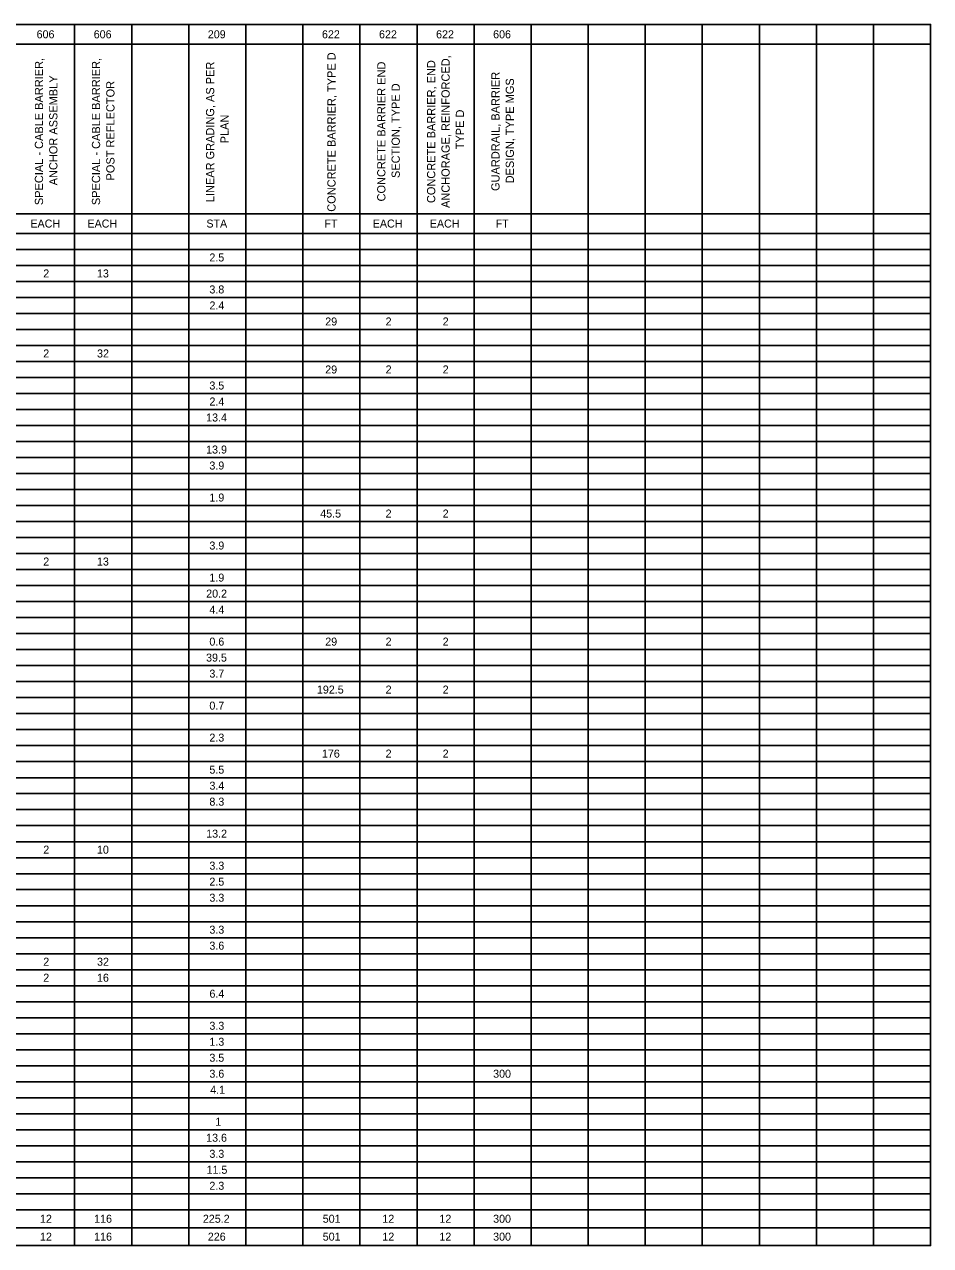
# Model space of a CAD drawing. Extents: x -542 to 295, y -281 to 32.
# Drawn here: x -1.5 to 14.08, y -100.59 to -79.59 of the extents above; entities that cross this region are included whole.
import ezdxf

# ---------------------------------------------------------------- set-up
doc = ezdxf.new("R2010")
doc.units = 0
doc.layers.add('SC_Scratch1', color=7, linetype='Continuous')
doc.layers.add('SH_Text', color=7, linetype='Continuous')

msp = doc.modelspace()

# ---------------------------------------------------------------- linework, layer by layer
at = {"layer": 'SC_Scratch1'}
msp.add_lwpolyline([(-16.421, -79.593), (14.079, -79.593), (14.079, -100.593), (-16.421, -100.593)], close=True, dxfattribs=at)
at = {"layer": 'SH_Text'}
for p, q in [((-16.421, -79.593), (14.079, -79.593)), ((-0.639, -79.593), (-0.639, -100.593)), ((0.342, -79.593), (0.342, -100.593)), ((1.324, -79.593), (1.324, -100.593)), ((2.305, -79.593), (2.305, -100.593)), ((3.286, -79.593), (3.286, -100.593)), ((4.267, -79.593), (4.267, -100.593)), ((5.248, -79.593), (5.248, -100.593)), ((6.23, -79.593), (6.23, -100.593)), ((7.211, -79.593), (7.211, -100.593)), ((8.192, -79.593), (8.192, -100.593)), ((9.173, -79.593), (9.173, -100.593)), ((10.154, -79.593), (10.154, -100.593)), ((11.136, -79.593), (11.136, -100.593)), ((12.117, -79.593), (12.117, -100.593)), ((13.098, -79.593), (13.098, -100.593)), ((14.079, -79.593), (14.079, -100.593)), ((-9.469, -79.933), (14.079, -79.933)), ((-9.469, -82.847), (14.079, -82.847)), ((-16.421, -83.187), (14.079, -83.187)), ((-16.421, -83.462), (14.079, -83.462)), ((-16.421, -83.737), (14.079, -83.737)), ((-16.421, -84.013), (14.079, -84.013)), ((-16.421, -84.288), (14.079, -84.288)), ((-16.421, -84.563), (14.079, -84.563)), ((-16.421, -84.838), (14.079, -84.838)), ((-16.421, -85.114), (14.079, -85.114)), ((-16.421, -85.389), (14.079, -85.389)), ((-16.421, -85.664), (14.079, -85.664)), ((-16.421, -85.94), (14.079, -85.94)), ((-16.421, -86.215), (14.079, -86.215)), ((-16.421, -86.49), (14.079, -86.49)), ((-16.421, -86.765), (14.079, -86.765)), ((-16.421, -87.041), (14.079, -87.041)), ((-16.421, -87.316), (14.079, -87.316)), ((-16.421, -87.591), (14.079, -87.591)), ((-16.421, -87.866), (14.079, -87.866)), ((-16.421, -88.142), (14.079, -88.142)), ((-16.421, -88.417), (14.079, -88.417)), ((-16.421, -88.692), (14.079, -88.692)), ((-16.421, -88.967), (14.079, -88.967)), ((-16.421, -89.243), (14.079, -89.243)), ((-16.421, -89.518), (14.079, -89.518)), ((-16.421, -89.793), (14.079, -89.793)), ((-16.421, -90.068), (14.079, -90.068)), ((-16.421, -90.344), (14.079, -90.344)), ((-16.421, -90.619), (14.079, -90.619)), ((-16.421, -90.894), (14.079, -90.894)), ((-16.421, -91.169), (14.079, -91.169)), ((-16.421, -91.445), (14.079, -91.445)), ((-16.421, -91.72), (14.079, -91.72)), ((-16.421, -91.995), (14.079, -91.995)), ((-16.421, -92.27), (14.079, -92.27)), ((-16.421, -92.546), (14.079, -92.546)), ((-16.421, -92.821), (14.079, -92.821)), ((-16.421, -93.096), (14.079, -93.096)), ((-16.421, -93.371), (14.079, -93.371)), ((-16.421, -93.647), (14.079, -93.647)), ((-16.421, -93.922), (14.079, -93.922)), ((-16.421, -94.197), (14.079, -94.197)), ((-16.421, -94.472), (14.079, -94.472)), ((-16.421, -94.748), (14.079, -94.748)), ((-16.421, -95.023), (14.079, -95.023)), ((-16.421, -95.298), (14.079, -95.298)), ((-16.421, -95.573), (14.079, -95.573)), ((-16.421, -95.849), (14.079, -95.849)), ((-16.421, -96.124), (14.079, -96.124)), ((-16.421, -96.399), (14.079, -96.399)), ((-16.421, -96.674), (14.079, -96.674)), ((-16.421, -96.95), (14.079, -96.95)), ((-16.421, -97.225), (14.079, -97.225)), ((-16.421, -97.5), (14.079, -97.5)), ((-16.421, -97.775), (14.079, -97.775)), ((-16.421, -98.051), (14.079, -98.051)), ((-16.421, -98.326), (14.079, -98.326)), ((-16.421, -98.601), (14.079, -98.601)), ((-16.421, -98.876), (14.079, -98.876)), ((-16.421, -99.152), (14.079, -99.152)), ((-16.421, -99.427), (14.079, -99.427)), ((-16.421, -99.702), (14.079, -99.702)), ((-16.421, -99.977), (14.079, -99.977)), ((-16.421, -100.285), (14.079, -100.285)), ((-16.421, -100.593), (14.079, -100.593))]:
    msp.add_line(p, q, dxfattribs=at)

# ---------------------------------------------------------------- texts
for s, height, p in [('606', 0.1376, (-1.293, -79.831)), ('606', 0.1376, (-0.311, -79.831)), ('209', 0.1376, (1.651, -79.831)), ('622', 0.1376, (3.614, -79.831)), ('622', 0.1376, (4.595, -79.831)), ('622', 0.1376, (5.576, -79.831)), ('606', 0.1376, (6.557, -79.831)), ('EACH', 0.1376, (-1.4, -83.086)), ('EACH', 0.1376, (-0.419, -83.086)), ('STA', 0.1376, (1.626, -83.086)), ('FT', 0.1376, (3.656, -83.086)), ('EACH', 0.1376, (4.487, -83.086)), ('EACH', 0.1376, (5.468, -83.086)), ('FT', 0.1376, (6.6, -83.086)), ('2.5', 0.1376, (1.678, -83.669)), ('2', 0.138, (-1.179, -83.944)), ('13', 0.1376, (-0.255, -83.944)), ('3.8', 0.1376, (1.678, -84.219)), ('2.4', 0.1376, (1.679, -84.494)), ('29', 0.1376, (3.67, -84.77)), ('2', 0.138, (4.708, -84.77)), ('2', 0.138, (5.689, -84.77)), ('2', 0.138, (-1.179, -85.32)), ('32', 0.1376, (-0.254, -85.32)), ('29', 0.1376, (3.67, -85.595)), ('2', 0.138, (4.708, -85.595)), ('2', 0.138, (5.689, -85.595)), ('3.5', 0.1376, (1.678, -85.871)), ('2.4', 0.1376, (1.679, -86.146)), ('13.4', 0.1376, (1.622, -86.421)), ('13.9', 0.1376, (1.622, -86.972)), ('3.9', 0.1376, (1.678, -87.247)), ('1.9', 0.1376, (1.678, -87.797)), ('45.5', 0.1376, (3.584, -88.073)), ('2', 0.138, (4.708, -88.073)), ('2', 0.138, (5.689, -88.073)), ('3.9', 0.1376, (1.678, -88.623)), ('2', 0.138, (-1.179, -88.898)), ('13', 0.1376, (-0.255, -88.898)), ('1.9', 0.1376, (1.678, -89.174)), ('20.2', 0.1376, (1.623, -89.449)), ('4.4', 0.1376, (1.679, -89.724)), ('0.6', 0.1376, (1.678, -90.275)), ('29', 0.1376, (3.67, -90.275)), ('2', 0.138, (4.708, -90.275)), ('2', 0.138, (5.689, -90.275)), ('39.5', 0.1376, (1.621, -90.55)), ('3.7', 0.1376, (1.678, -90.825)), ('192.5', 0.1376, (3.527, -91.1)), ('2', 0.138, (4.708, -91.1)), ('2', 0.138, (5.689, -91.1)), ('0.7', 0.1376, (1.678, -91.376)), ('2.3', 0.1376, (1.678, -91.926)), ('176', 0.1376, (3.613, -92.201)), ('2', 0.138, (4.708, -92.201)), ('2', 0.138, (5.689, -92.201)), ('5.5', 0.1376, (1.678, -92.477)), ('3.4', 0.1376, (1.679, -92.752)), ('8.3', 0.1376, (1.678, -93.027)), ('13.2', 0.1376, (1.623, -93.578)), ('2', 0.138, (-1.179, -93.853)), ('10', 0.1376, (-0.255, -93.853)), ('3.3', 0.1376, (1.678, -94.128)), ('2.5', 0.1376, (1.678, -94.403)), ('3.3', 0.1376, (1.678, -94.679)), ('3.3', 0.1376, (1.678, -95.229)), ('3.6', 0.1376, (1.678, -95.504)), ('2', 0.138, (-1.179, -95.78)), ('32', 0.1376, (-0.254, -95.78)), ('2', 0.138, (-1.179, -96.055)), ('16', 0.1376, (-0.255, -96.055)), ('6.4', 0.1376, (1.679, -96.33)), ('3.3', 0.1376, (1.678, -96.881)), ('1.3', 0.1376, (1.678, -97.156)), ('3.5', 0.1376, (1.678, -97.431)), ('3.6', 0.1376, (1.678, -97.706)), ('300', 0.1376, (6.557, -97.706)), ('4.1', 0.1376, (1.692, -97.982)), ('1', 0.138, (1.778, -98.532)), ('13.6', 0.1376, (1.622, -98.807)), ('3.3', 0.1376, (1.678, -99.083)), ('11.5', 0.1376, (1.629, -99.358)), ('2.3', 0.1376, (1.678, -99.633)), ('12', 0.1376, (-1.235, -100.2)), ('116', 0.1376, (-0.304, -100.2)), ('225.2', 0.1376, (1.566, -100.2)), ('501', 0.1376, (3.627, -100.2)), ('12', 0.1376, (4.652, -100.2)), ('12', 0.1376, (5.633, -100.2)), ('300', 0.1376, (6.557, -100.2)), ('12', 0.1376, (-1.235, -100.508)), ('116', 0.1376, (-0.304, -100.508)), ('226', 0.1376, (1.651, -100.508)), ('501', 0.1376, (3.627, -100.508)), ('12', 0.1376, (4.652, -100.508)), ('12', 0.1376, (5.633, -100.508)), ('300', 0.1376, (6.557, -100.508))]:
    msp.add_text(s, height=height, dxfattribs=at).set_placement(p)
for s, height, p in [('SPECIAL - CABLE BARRIER, ', 0.14136, (-1.182, -82.7)), ('SPECIAL - CABLE BARRIER, ', 0.14136, (-0.201, -82.7)), ('CONCRETE BARRIER, TYPE D', 0.14136, (3.847, -82.814)), ('CONCRETE BARRIER, END ', 0.14136, (5.562, -82.665)), ('ANCHORAGE, REINFORCED, ', 0.14136, (5.81, -82.749)), ('LINEAR GRADING, AS PER ', 0.14136, (1.761, -82.649)), ('CONCRETE BARRIER END ', 0.14136, (4.705, -82.637)), ('GUARDRAIL, BARRIER ', 0.14136, (6.667, -82.456)), ('ANCHOR ASSEMBLY', 0.14136, (-0.935, -82.36)), ('POST REFLECTOR', 0.14136, (0.046, -82.276)), ('SECTION, TYPE D', 0.14136, (4.952, -82.234)), ('DESIGN, TYPE MGS', 0.14136, (6.915, -82.326)), ('PLAN', 0.1414, (2.009, -81.638)), ('TYPE D', 0.1414, (6.057, -81.74))]:
    msp.add_text(s, height=height, rotation=90, dxfattribs=at).set_placement(p)

doc.saveas('drawing.dxf')
